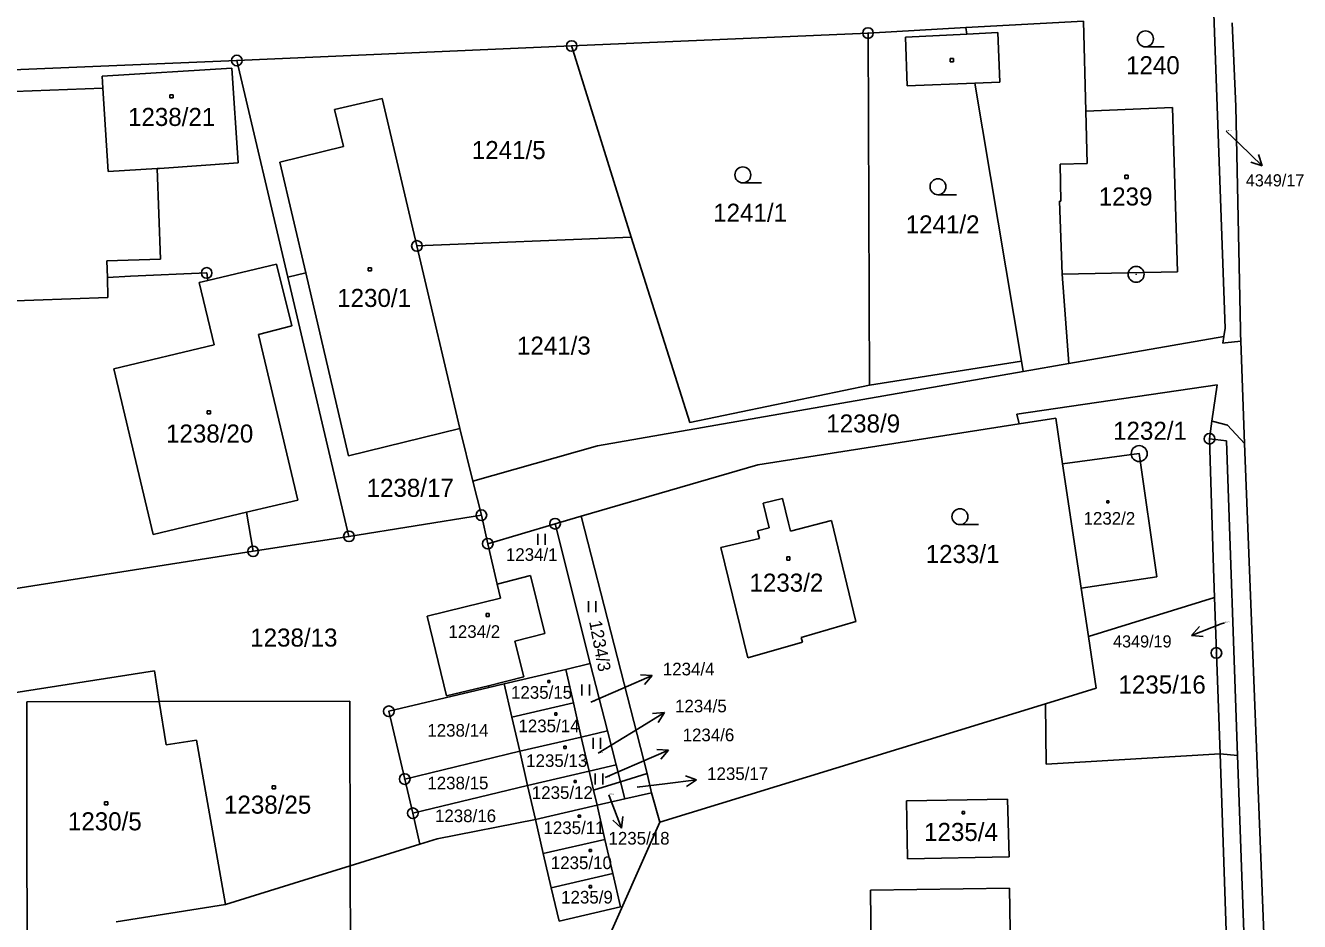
# Model space of a CAD drawing. Extents: x -468021 to -466942, y -1130484 to -1128584.
# Drawn here: x -467694.3 to -467574.3, y -1130403 to -1130318.6 of the extents above; entities that cross this region are included whole.
import ezdxf

# ---------------------------------------------------------------- set-up
doc = ezdxf.new("R2010")
doc.units = 0
doc.layers.add('DKM', color=7, linetype='Continuous')

msp = doc.modelspace()

# ---------------------------------------------------------------- linework, layer by layer
at = {"layer": 'DKM'}
for p, q in [((-467581.28, -1130347.13), (-467582.34, -1130317.53)), ((-467614.91, -1130319.33), (-467605.71, -1130318.82)), ((-467605.71, -1130318.82), (-467594.62, -1130318.21)), ((-467605.71, -1130318.82), (-467605.61, -1130319.43)), ((-467594.62, -1130318.21), (-467594.4, -1130326.68)), ((-467580.28, -1130326.24), (-467580.63, -1130318.37)), ((-467614.91, -1130319.33), (-467642.82, -1130320.55)), ((-467614.77, -1130352.5), (-467614.91, -1130319.33)), ((-467611.39, -1130319.73), (-467605.61, -1130319.43)), ((-467611.21, -1130324.31), (-467611.39, -1130319.73)), ((-467605.61, -1130319.43), (-467602.69, -1130319.28)), ((-467602.69, -1130319.28), (-467602.48, -1130323.96)), ((-467674.35, -1130321.92), (-467642.82, -1130320.55)), ((-467642.82, -1130320.55), (-467642.71, -1130320.91)), ((-467642.71, -1130320.91), (-467637.22, -1130338.55)), ((-467588.78, -1130320.63), (-467587.03, -1130320.63)), ((-467718.71, -1130323.75), (-467674.35, -1130321.92)), ((-467674.35, -1130321.92), (-467669.54, -1130342.31)), ((-467607.16, -1130321.73), (-467606.86, -1130321.73)), ((-467607.16, -1130322.03), (-467607.16, -1130321.73)), ((-467606.86, -1130322.03), (-467607.16, -1130322.03)), ((-467606.86, -1130321.73), (-467606.86, -1130322.03)), ((-467674.81, -1130322.63), (-467687.04, -1130323.4)), ((-467686.97, -1130324.53), (-467687.04, -1130323.4)), ((-467674.24, -1130331.56), (-467674.81, -1130322.63)), ((-467763.62, -1130327.45), (-467686.97, -1130324.53)), ((-467686.97, -1130324.53), (-467686.48, -1130332.37)), ((-467604.84, -1130324.05), (-467611.21, -1130324.31)), ((-467602.48, -1130323.96), (-467604.84, -1130324.05)), ((-467604.84, -1130324.05), (-467600.46, -1130350.23)), ((-467680.65, -1130325.14), (-467680.35, -1130325.14)), ((-467680.65, -1130325.44), (-467680.65, -1130325.14)), ((-467680.35, -1130325.44), (-467680.65, -1130325.44)), ((-467680.35, -1130325.14), (-467680.35, -1130325.44)), ((-467665.15, -1130326.54), (-467660.66, -1130325.51)), ((-467660.66, -1130325.51), (-467657.39, -1130339.38)), ((-467664.3, -1130330), (-467665.15, -1130326.54)), ((-467586.24, -1130326.35), (-467594.4, -1130326.68)), ((-467594.4, -1130326.68), (-467594.26, -1130331.62)), ((-467585.76, -1130341.8), (-467586.24, -1130326.35)), ((-467579.84, -1130347.24), (-467580.28, -1130326.24)), ((-467581.17, -1130328.56), (-467579.94, -1130329.75)), ((-467579.94, -1130329.75), (-467577.78, -1130331.84)), ((-467670.3, -1130331.49), (-467664.3, -1130330)), ((-467577.78, -1130331.84), (-467578.15, -1130330.78)), ((-467681.84, -1130332.09), (-467686.48, -1130332.37)), ((-467681.84, -1130332.09), (-467681.62, -1130332.08)), ((-467681.84, -1130332.09), (-467681.53, -1130340.62)), ((-467681.62, -1130332.08), (-467674.24, -1130331.56)), ((-467667.86, -1130341.91), (-467670.3, -1130331.49)), ((-467594.26, -1130331.62), (-467596.82, -1130331.69)), ((-467596.82, -1130331.69), (-467596.75, -1130335.15)), ((-467577.78, -1130331.84), (-467578.85, -1130331.5)), ((-467590.71, -1130332.72), (-467590.41, -1130332.72)), ((-467590.71, -1130333.02), (-467590.71, -1130332.72)), ((-467590.41, -1130333.02), (-467590.71, -1130333.02)), ((-467590.41, -1130332.72), (-467590.41, -1130333.02)), ((-467626.7, -1130333.44), (-467624.95, -1130333.44)), ((-467608.32, -1130334.55), (-467606.57, -1130334.55)), ((-467596.88, -1130335.15), (-467596.63, -1130342.04)), ((-467596.75, -1130335.15), (-467596.88, -1130335.15)), ((-467637.22, -1130338.55), (-467657.39, -1130339.38)), ((-467657.39, -1130339.38), (-467653.34, -1130356.55)), ((-467637.22, -1130338.55), (-467631.68, -1130356.01)), ((-467681.53, -1130340.62), (-467686.58, -1130340.79)), ((-467686.58, -1130340.79), (-467686.54, -1130342.35)), ((-467677.07, -1130342.62), (-467670.6, -1130341.08)), ((-467670.6, -1130341.08), (-467669.18, -1130346.91)), ((-467661.97, -1130341.43), (-467661.67, -1130341.43)), ((-467661.97, -1130341.73), (-467661.97, -1130341.43)), ((-467661.67, -1130341.73), (-467661.97, -1130341.73)), ((-467661.67, -1130341.43), (-467661.67, -1130341.73)), ((-467596.63, -1130342.04), (-467585.76, -1130341.8)), ((-467686.54, -1130342.35), (-467684.36, -1130342.23)), ((-467686.54, -1130342.35), (-467686.49, -1130344.23)), ((-467684.36, -1130342.23), (-467677.19, -1130341.92)), ((-467677.89, -1130342.82), (-467677.07, -1130342.62)), ((-467676.49, -1130348.68), (-467677.89, -1130342.82)), ((-467677.19, -1130341.92), (-467677.07, -1130342.62)), ((-467669.54, -1130342.31), (-467667.86, -1130341.91)), ((-467669.54, -1130342.31), (-467663.79, -1130366.72)), ((-467663.82, -1130359.13), (-467667.86, -1130341.91)), ((-467596.01, -1130350.45), (-467596.63, -1130342.04)), ((-467686.49, -1130344.23), (-467754.48, -1130346.7)), ((-467669.18, -1130346.91), (-467672.3, -1130347.73)), ((-467672.3, -1130347.73), (-467668.61, -1130363.3)), ((-467581.28, -1130347.13), (-467581.39, -1130347.9)), ((-467579.84, -1130347.24), (-467579.82, -1130347.63)), ((-467579.82, -1130347.63), (-467579.8, -1130348.33)), ((-467685.94, -1130350.94), (-467676.49, -1130348.68)), ((-467596.01, -1130350.45), (-467581.39, -1130347.9)), ((-467581.39, -1130347.9), (-467581.48, -1130348.52)), ((-467581.27, -1130348.5), (-467581.48, -1130348.52)), ((-467579.8, -1130348.33), (-467581.27, -1130348.5)), ((-467579.8, -1130348.33), (-467579.45, -1130357.99)), ((-467682.22, -1130366.54), (-467685.94, -1130350.94)), ((-467640.38, -1130358.19), (-467600.3, -1130351.2)), ((-467614.77, -1130352.5), (-467600.46, -1130350.23)), ((-467600.46, -1130350.23), (-467600.3, -1130351.2)), ((-467600.3, -1130351.2), (-467596.01, -1130350.45)), ((-467631.68, -1130356.01), (-467614.77, -1130352.5)), ((-467582.03, -1130352.45), (-467600.89, -1130355.23)), ((-467582.03, -1130352.45), (-467582.52, -1130355.89)), ((-467677.13, -1130354.9), (-467676.83, -1130354.9)), ((-467677.13, -1130355.2), (-467677.13, -1130354.9)), ((-467676.83, -1130354.9), (-467676.83, -1130355.2)), ((-467676.83, -1130355.2), (-467677.13, -1130355.2)), ((-467625.3, -1130359.99), (-467600.66, -1130356.13)), ((-467600.89, -1130355.23), (-467600.66, -1130356.13)), ((-467600.66, -1130356.13), (-467597.22, -1130355.59)), ((-467597.22, -1130355.59), (-467596.58, -1130359.88)), ((-467582.52, -1130355.89), (-467582.75, -1130357.53)), ((-467582.38, -1130355.92), (-467582.52, -1130355.89)), ((-467581.06, -1130356.25), (-467582.38, -1130355.92)), ((-467653.34, -1130356.55), (-467663.82, -1130359.13)), ((-467653.34, -1130356.55), (-467652.12, -1130361.51)), ((-467579.45, -1130357.99), (-467581.06, -1130356.25)), ((-467640.38, -1130358.19), (-467652.12, -1130361.51)), ((-467582.38, -1130369.75), (-467582.75, -1130357.53)), ((-467582.75, -1130357.53), (-467581.16, -1130357.73)), ((-467581.16, -1130357.73), (-467580.12, -1130387.34)), ((-467579.45, -1130357.99), (-467574.49, -1130484.41)), ((-467589.37, -1130358.93), (-467596.58, -1130359.88)), ((-467589.37, -1130358.93), (-467587.71, -1130370.54)), ((-467641.93, -1130364.82), (-467625.3, -1130359.99)), ((-467596.58, -1130359.88), (-467594.83, -1130371.6)), ((-467652.12, -1130361.51), (-467651.32, -1130364.73)), ((-467668.61, -1130363.3), (-467673.43, -1130364.45)), ((-467624.79, -1130363.61), (-467622.96, -1130363.16)), ((-467622.96, -1130363.16), (-467622.39, -1130365.47)), ((-467592.43, -1130363.37), (-467592.22, -1130363.37)), ((-467592.43, -1130363.58), (-467592.43, -1130363.37)), ((-467592.22, -1130363.37), (-467592.22, -1130363.58)), ((-467673.43, -1130364.45), (-467682.22, -1130366.54)), ((-467673.43, -1130364.45), (-467672.82, -1130368.13)), ((-467624.22, -1130365.92), (-467624.79, -1130363.61)), ((-467592.22, -1130363.58), (-467592.43, -1130363.58)), ((-467663.79, -1130366.72), (-467651.32, -1130364.73)), ((-467651.32, -1130364.73), (-467650.72, -1130367.41)), ((-467644.38, -1130365.53), (-467650.72, -1130367.41)), ((-467641.93, -1130364.82), (-467644.38, -1130365.53)), ((-467644.38, -1130365.53), (-467641.06, -1130378.68)), ((-467635.7, -1130389.05), (-467641.93, -1130364.82)), ((-467622.39, -1130365.47), (-467622.2, -1130366.22)), ((-467622.2, -1130366.22), (-467618.36, -1130365.24)), ((-467618.36, -1130365.24), (-467616.05, -1130374.73)), ((-467606.25, -1130365.62), (-467604.5, -1130365.62)), ((-467663.79, -1130366.72), (-467672.82, -1130368.13)), ((-467646.01, -1130367.53), (-467646.01, -1130366.48)), ((-467645.31, -1130366.48), (-467645.31, -1130367.53)), ((-467628.77, -1130367.78), (-467625.13, -1130366.91)), ((-467625.31, -1130366.19), (-467624.22, -1130365.92)), ((-467625.13, -1130366.91), (-467625.31, -1130366.19)), ((-467672.82, -1130368.13), (-467699.09, -1130372.25)), ((-467650.72, -1130367.41), (-467649.83, -1130371.22)), ((-467626.22, -1130378.16), (-467628.77, -1130367.78)), ((-467622.56, -1130368.65), (-467622.26, -1130368.65)), ((-467622.56, -1130368.95), (-467622.56, -1130368.65)), ((-467622.26, -1130368.95), (-467622.56, -1130368.95)), ((-467622.26, -1130368.65), (-467622.26, -1130368.95)), ((-467649.83, -1130371.22), (-467646.68, -1130370.42)), ((-467646.68, -1130370.42), (-467645.34, -1130375.88)), ((-467594.83, -1130371.6), (-467587.71, -1130370.54)), ((-467582.29, -1130372.47), (-467582.38, -1130369.75)), ((-467649.52, -1130372.53), (-467649.83, -1130371.22)), ((-467594.83, -1130371.6), (-467594.15, -1130376.15)), ((-467656.43, -1130374.22), (-467649.52, -1130372.53)), ((-467641.24, -1130373.87), (-467641.24, -1130372.82)), ((-467640.54, -1130372.82), (-467640.54, -1130373.87)), ((-467582.29, -1130372.47), (-467594.15, -1130376.15)), ((-467582.1, -1130377.7), (-467582.29, -1130372.47)), ((-467650.88, -1130373.98), (-467650.58, -1130373.98)), ((-467650.88, -1130374.28), (-467650.88, -1130373.98)), ((-467650.58, -1130373.98), (-467650.58, -1130374.28)), ((-467654.6, -1130381.75), (-467656.43, -1130374.22)), ((-467650.58, -1130374.28), (-467650.88, -1130374.28)), ((-467616.05, -1130374.73), (-467621.22, -1130376.23)), ((-467581.65, -1130374.97), (-467584.45, -1130376.04)), ((-467584.45, -1130376.04), (-467583.7, -1130375.22)), ((-467581.33, -1130374.85), (-467581.65, -1130374.97)), ((-467645.34, -1130375.88), (-467648.18, -1130376.58)), ((-467647.33, -1130379.96), (-467648.18, -1130376.58)), ((-467621.22, -1130376.23), (-467621.09, -1130376.67)), ((-467594.15, -1130376.15), (-467593.43, -1130381.01)), ((-467584.45, -1130376.04), (-467583.34, -1130376.15)), ((-467621.09, -1130376.67), (-467626.22, -1130378.16)), ((-467582.1, -1130377.7), (-467581.76, -1130387.2)), ((-467643.38, -1130379.26), (-467641.06, -1130378.68)), ((-467641.06, -1130378.68), (-467639.44, -1130385.03)), ((-467682.11, -1130379.37), (-467700.3, -1130382.24)), ((-467681.65, -1130382.27), (-467682.11, -1130379.37)), ((-467650.65, -1130380.78), (-467647.33, -1130379.96)), ((-467643.38, -1130379.26), (-467649.19, -1130380.61)), ((-467642.66, -1130382.39), (-467643.38, -1130379.26)), ((-467637.98, -1130381.01), (-467635.23, -1130379.81)), ((-467635.23, -1130379.81), (-467636.35, -1130379.75)), ((-467635.23, -1130379.81), (-467635.95, -1130380.67)), ((-467650.62, -1130380.95), (-467660.04, -1130383.19)), ((-467654.6, -1130381.75), (-467650.65, -1130380.78)), ((-467650.65, -1130380.78), (-467650.62, -1130380.95)), ((-467649.19, -1130380.61), (-467650.62, -1130380.95)), ((-467649.19, -1130380.61), (-467648.46, -1130383.74)), ((-467645.07, -1130380.28), (-467644.86, -1130380.28)), ((-467645.07, -1130380.49), (-467645.07, -1130380.28)), ((-467644.86, -1130380.49), (-467645.07, -1130380.49)), ((-467644.86, -1130380.28), (-467644.86, -1130380.49)), ((-467641.85, -1130381.72), (-467641.85, -1130380.67)), ((-467641.15, -1130380.67), (-467641.15, -1130381.72)), ((-467641.02, -1130382.34), (-467637.98, -1130381.01)), ((-467593.43, -1130381.01), (-467598.21, -1130382.48)), ((-467681.65, -1130382.27), (-467694.14, -1130382.31)), ((-467694.14, -1130382.31), (-467694.12, -1130395.3)), ((-467663.71, -1130382.23), (-467681.65, -1130382.27)), ((-467681.65, -1130382.27), (-467681, -1130386.36)), ((-467663.67, -1130397.73), (-467663.71, -1130382.23)), ((-467642.66, -1130382.39), (-467648.46, -1130383.74)), ((-467641.91, -1130385.62), (-467642.66, -1130382.39)), ((-467598.21, -1130382.48), (-467634.52, -1130393.63)), ((-467598.21, -1130382.48), (-467598.13, -1130388.18)), ((-467660.04, -1130383.19), (-467658.54, -1130389.57)), ((-467648.46, -1130383.74), (-467647.71, -1130386.96)), ((-467644.41, -1130383.34), (-467644.2, -1130383.34)), ((-467644.41, -1130383.55), (-467644.41, -1130383.34)), ((-467644.2, -1130383.55), (-467644.41, -1130383.55)), ((-467644.2, -1130383.34), (-467644.2, -1130383.55)), ((-467636.63, -1130384.86), (-467634.08, -1130383.29)), ((-467634.08, -1130383.29), (-467635.19, -1130383.39)), ((-467634.08, -1130383.29), (-467634.66, -1130384.24)), ((-467640.32, -1130387.13), (-467636.63, -1130384.86)), ((-467678.14, -1130385.91), (-467681, -1130386.36)), ((-467678.14, -1130385.91), (-467675.43, -1130401.38)), ((-467641.91, -1130385.62), (-467647.71, -1130386.96)), ((-467639.44, -1130385.03), (-467641.91, -1130385.62)), ((-467641.17, -1130388.83), (-467641.91, -1130385.62)), ((-467640.8, -1130386.73), (-467640.8, -1130385.68)), ((-467640.1, -1130385.68), (-467640.1, -1130386.73)), ((-467639.44, -1130385.03), (-467638.62, -1130388.23)), ((-467647.71, -1130386.96), (-467658.54, -1130389.57)), ((-467647.71, -1130386.96), (-467646.97, -1130390.17)), ((-467643.56, -1130386.48), (-467643.35, -1130386.48)), ((-467643.56, -1130386.69), (-467643.56, -1130386.48)), ((-467643.35, -1130386.69), (-467643.56, -1130386.69)), ((-467643.35, -1130386.48), (-467643.35, -1130386.69)), ((-467636.45, -1130388.04), (-467633.69, -1130386.86)), ((-467633.69, -1130386.86), (-467634.81, -1130386.79)), ((-467633.69, -1130386.86), (-467634.41, -1130387.71)), ((-467581.76, -1130387.2), (-467598.13, -1130388.18)), ((-467581.76, -1130387.2), (-467580.16, -1130432.32)), ((-467580.12, -1130387.34), (-467581.76, -1130387.2)), ((-467580.12, -1130387.34), (-467578.48, -1130431.76)), ((-467638.62, -1130388.23), (-467641.17, -1130388.83)), ((-467639.66, -1130389.42), (-467636.45, -1130388.04)), ((-467638.62, -1130388.23), (-467638.21, -1130389.83)), ((-467658.54, -1130389.57), (-467657.78, -1130392.79)), ((-467641.17, -1130388.83), (-467646.97, -1130390.17)), ((-467642.59, -1130389.7), (-467642.38, -1130389.7)), ((-467642.59, -1130389.91), (-467642.59, -1130389.7)), ((-467642.38, -1130389.7), (-467642.38, -1130389.91)), ((-467640.76, -1130390.62), (-467641.17, -1130388.83)), ((-467640.59, -1130390.09), (-467640.59, -1130389.04)), ((-467639.89, -1130389.04), (-467639.89, -1130390.09)), ((-467638.21, -1130389.83), (-467635.7, -1130389.05)), ((-467635.7, -1130389.05), (-467635.29, -1130390.87)), ((-467634.04, -1130390.01), (-467631.06, -1130389.66)), ((-467631.06, -1130389.66), (-467632.11, -1130389.28)), ((-467631.06, -1130389.66), (-467631.99, -1130390.27)), ((-467671.02, -1130390.2), (-467670.72, -1130390.2)), ((-467671.02, -1130390.5), (-467671.02, -1130390.2)), ((-467670.72, -1130390.5), (-467671.02, -1130390.5)), ((-467670.72, -1130390.2), (-467670.72, -1130390.5)), ((-467646.97, -1130390.17), (-467657.78, -1130392.79)), ((-467646.23, -1130393.38), (-467646.97, -1130390.17)), ((-467642.38, -1130389.91), (-467642.59, -1130389.91)), ((-467640.76, -1130390.62), (-467638.21, -1130389.83)), ((-467640.76, -1130390.62), (-467640.43, -1130392.04)), ((-467638.21, -1130389.83), (-467637.8, -1130391.43)), ((-467637.8, -1130391.43), (-467635.29, -1130390.87)), ((-467636.64, -1130390.32), (-467634.04, -1130390.01)), ((-467634.52, -1130393.63), (-467635.29, -1130390.87)), ((-467686.81, -1130391.71), (-467686.51, -1130391.71)), ((-467686.81, -1130392.01), (-467686.81, -1130391.71)), ((-467686.51, -1130392.01), (-467686.81, -1130392.01)), ((-467686.51, -1130391.71), (-467686.51, -1130392.01)), ((-467640.43, -1130392.04), (-467646.23, -1130393.38)), ((-467637.8, -1130391.43), (-467640.43, -1130392.04)), ((-467639.68, -1130395.25), (-467640.43, -1130392.04)), ((-467639.32, -1130391.06), (-467639.19, -1130391.4)), ((-467639.19, -1130391.4), (-467638.11, -1130394.2)), ((-467611.29, -1130391.61), (-467601.76, -1130391.45)), ((-467611.2, -1130397.09), (-467611.29, -1130391.61)), ((-467601.76, -1130391.45), (-467601.63, -1130396.9)), ((-467657.78, -1130392.79), (-467657.11, -1130395.69)), ((-467655.5, -1130395.19), (-467646.23, -1130393.38)), ((-467646.23, -1130393.38), (-467645.49, -1130396.59)), ((-467642.21, -1130392.96), (-467642, -1130392.96)), ((-467642.21, -1130393.17), (-467642.21, -1130392.96)), ((-467642, -1130393.17), (-467642.21, -1130393.17)), ((-467642, -1130392.96), (-467642, -1130393.17)), ((-467638.11, -1130394.2), (-467638, -1130393.09)), ((-467606.04, -1130392.63), (-467605.83, -1130392.63)), ((-467606.04, -1130392.84), (-467606.04, -1130392.63)), ((-467605.83, -1130392.84), (-467606.04, -1130392.84)), ((-467605.83, -1130392.63), (-467605.83, -1130392.84)), ((-467634.52, -1130393.63), (-467641.42, -1130409.14)), ((-467638.11, -1130394.2), (-467638.94, -1130393.45)), ((-467694.12, -1130395.3), (-467694.11, -1130404.36)), ((-467663.67, -1130397.73), (-467657.11, -1130395.69)), ((-467657.11, -1130395.69), (-467655.5, -1130395.19)), ((-467639.68, -1130395.25), (-467645.49, -1130396.59)), ((-467638.94, -1130398.45), (-467639.68, -1130395.25)), ((-467645.49, -1130396.59), (-467644.74, -1130399.8)), ((-467641.16, -1130396.19), (-467640.95, -1130396.19)), ((-467641.16, -1130396.4), (-467641.16, -1130396.19)), ((-467640.95, -1130396.4), (-467641.16, -1130396.4)), ((-467640.95, -1130396.19), (-467640.95, -1130396.4)), ((-467601.63, -1130396.9), (-467611.2, -1130397.09)), ((-467667.14, -1130398.81), (-467663.67, -1130397.73)), ((-467663.62, -1130424.28), (-467663.67, -1130397.73)), ((-467675.43, -1130401.38), (-467667.14, -1130398.81)), ((-467638.94, -1130398.45), (-467644.74, -1130399.8)), ((-467638.21, -1130401.6), (-467638.94, -1130398.45)), ((-467644.74, -1130399.8), (-467644.01, -1130402.95)), ((-467641.16, -1130399.6), (-467640.95, -1130399.6)), ((-467641.16, -1130399.81), (-467641.16, -1130399.6)), ((-467640.95, -1130399.81), (-467641.16, -1130399.81)), ((-467640.95, -1130399.6), (-467640.95, -1130399.81)), ((-467614.67, -1130400.04), (-467601.59, -1130399.85)), ((-467614.62, -1130406.02), (-467614.67, -1130400.04)), ((-467601.59, -1130399.85), (-467601.08, -1130430.79)), ((-467675.43, -1130401.38), (-467685.73, -1130403.02)), ((-467644.01, -1130402.95), (-467638.21, -1130401.6))]:
    msp.add_line(p, q, dxfattribs=at)
for centre, radius in [((-467614.91, -1130319.33), 0.5), ((-467642.82, -1130320.55), 0.5), ((-467614.91, -1130319.33), 0.01), ((-467588.78, -1130319.88), 0.75), ((-467674.35, -1130321.92), 0.5), ((-467642.82, -1130320.55), 0.01), ((-467674.35, -1130321.92), 0.01), ((-467626.7, -1130332.69), 0.75), ((-467608.32, -1130333.8), 0.75), ((-467657.39, -1130339.38), 0.5), ((-467657.39, -1130339.38), 0.01), ((-467677.19, -1130341.92), 0.5), ((-467589.66, -1130342.05), 0.75), ((-467677.19, -1130341.92), 0.01), ((-467589.66, -1130342.05), 0.01), ((-467582.75, -1130357.53), 0.5), ((-467589.37, -1130358.93), 0.75), ((-467582.75, -1130357.53), 0.01), ((-467589.37, -1130358.93), 0.01), ((-467651.32, -1130364.73), 0.5), ((-467606.25, -1130364.87), 0.75), ((-467651.32, -1130364.73), 0.01), ((-467644.38, -1130365.53), 0.5), ((-467644.38, -1130365.53), 0.01), ((-467663.79, -1130366.72), 0.5), ((-467663.79, -1130366.72), 0.01), ((-467650.72, -1130367.41), 0.5), ((-467672.82, -1130368.13), 0.5), ((-467672.82, -1130368.13), 0.01), ((-467650.72, -1130367.41), 0.01), ((-467582.1, -1130377.7), 0.5), ((-467582.1, -1130377.7), 0.01), ((-467660.04, -1130383.19), 0.5), ((-467660.04, -1130383.19), 0.01), ((-467658.54, -1130389.57), 0.5), ((-467658.54, -1130389.57), 0.01), ((-467657.78, -1130392.79), 0.5), ((-467657.78, -1130392.79), 0.01)]:
    msp.add_circle(centre, radius, dxfattribs=at)

# ---------------------------------------------------------------- texts
for s, height, p in [('1240', 1.7, (-467590.61, -1130323.21)), ('1238/21', 1.7, (-467684.6, -1130328.08)), ('4349/17', 0.1, (-467581.17, -1130328.56)), ('1241/5', 1.7, (-467652.22, -1130331.2)), ('4349/17', 1.14, (-467579.33, -1130333.77)), ('1239', 1.7, (-467593.18, -1130335.57)), ('1241/1', 1.7, (-467629.49, -1130337.1)), ('1241/2', 1.7, (-467611.36, -1130338.2)), ('1230/1', 1.7, (-467664.9, -1130345.12)), ('1241/3', 1.7, (-467647.97, -1130349.61)), ('1238/20', 1.7, (-467681.02, -1130357.89)), ('1238/9', 1.7, (-467618.84, -1130356.94)), ('1232/1', 1.7, (-467591.83, -1130357.63)), ('1238/17', 1.7, (-467662.13, -1130363)), ('1232/2', 1.19, (-467594.61, -1130365.62)), ('1234/1', 1.19, (-467649.01, -1130369.03)), ('1233/1', 1.7, (-467609.48, -1130369.23)), ('1233/2', 1.7, (-467626.07, -1130371.93)), ('1238/13', 1.7, (-467673.09, -1130377.1)), ('1234/2', 1.19, (-467654.42, -1130376.28)), ('4349/19', 0.1, (-467581.33, -1130374.85)), ('4349/19', 1.14, (-467591.83, -1130377.18)), ('1234/4', 1.19, (-467634.23, -1130379.81)), ('1235/16', 1.7, (-467591.32, -1130381.52)), ('1235/15', 1.19, (-467648.53, -1130382.01)), ('1234/4', 0.1, (-467641.02, -1130382.34)), ('1234/5', 1.19, (-467633.08, -1130383.29)), ('1238/14', 1.19, (-467656.41, -1130385.58)), ('1235/14', 1.19, (-467647.83, -1130385.16)), ('1234/6', 1.19, (-467632.37, -1130386.01)), ('1235/13', 1.19, (-467647.1, -1130388.43)), ('1234/5', 0.1, (-467640.32, -1130387.13)), ('1235/17', 1.19, (-467630.06, -1130389.66)), ('1238/15', 1.19, (-467656.41, -1130390.54)), ('1234/6', 0.1, (-467639.66, -1130389.42)), ('1235/12', 1.19, (-467646.57, -1130391.44)), ('1235/18', 0.1, (-467639.32, -1130391.06)), ('1235/17', 0.1, (-467636.64, -1130390.32)), ('1238/25', 1.7, (-467675.56, -1130392.83)), ('1230/5', 1.7, (-467690.26, -1130394.4)), ('1238/16', 1.19, (-467655.69, -1130393.63)), ('1235/11', 1.19, (-467645.47, -1130394.75)), ('1235/18', 1.19, (-467639.35, -1130395.74)), ('1235/4', 1.7, (-467609.63, -1130395.4)), ('1235/10', 1.19, (-467644.78, -1130398.05)), ('1235/9', 1.19, (-467643.81, -1130401.29))]:
    msp.add_text(s, height=height, dxfattribs=at).set_placement(p)
msp.add_text('1234/3', height=1.19, rotation=280.742, dxfattribs=at).set_placement((-467641.18, -1130374.75))

doc.saveas('drawing.dxf')
